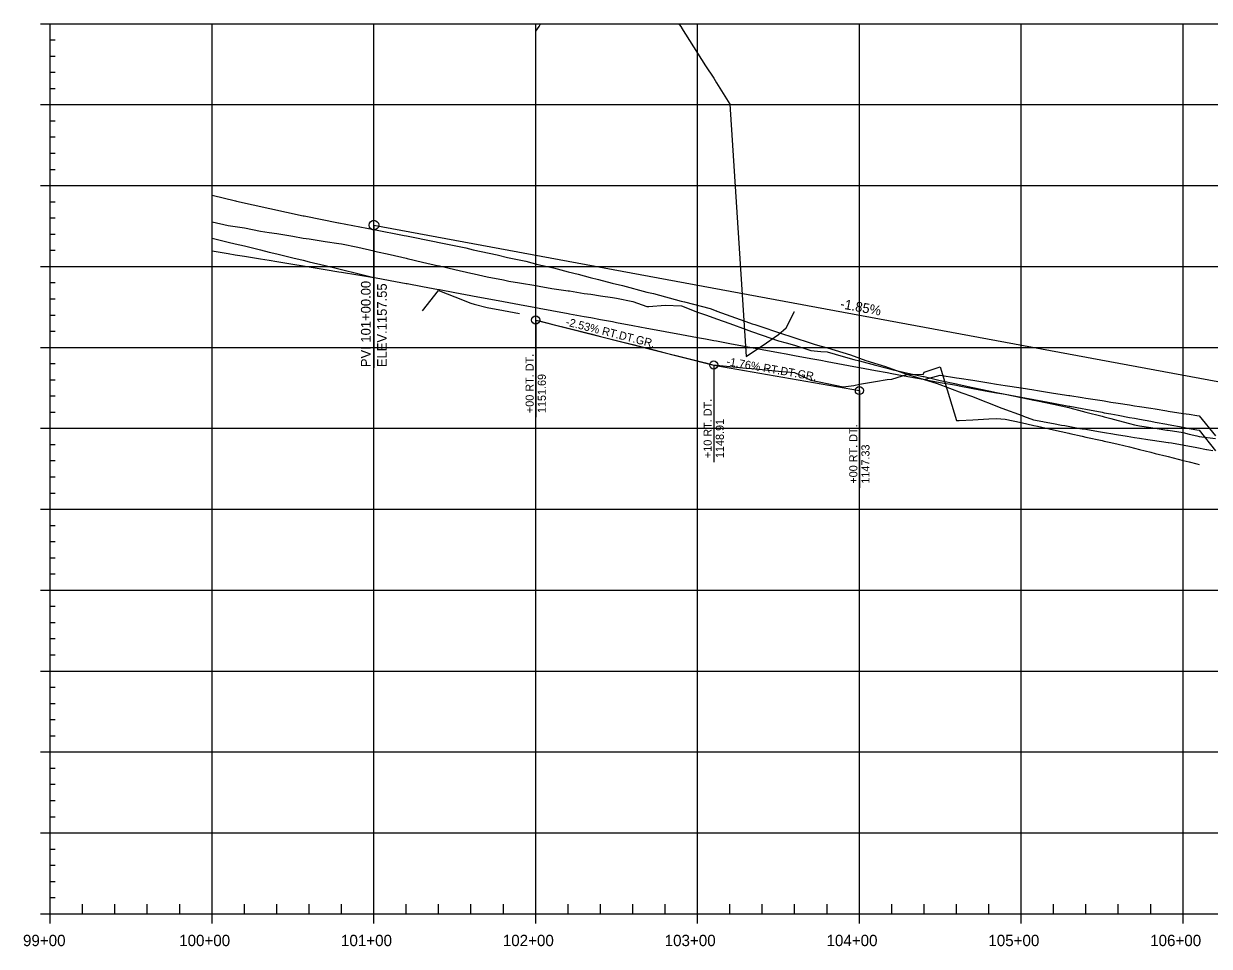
# Model space of a CAD drawing. Extents: x 688474 to 694748, y 765018 to 767373.
# Drawn here: x 690837 to 691570, y 765790 to 766360 of the extents above; entities that cross this region are included whole.
import ezdxf

# ---------------------------------------------------------------- set-up
doc = ezdxf.new("R2010")
doc.units = 0
for name, color, linetype in [('30', 7, 'Continuous'), ('37', 7, 'Continuous'), ('R_Exist Surface', 7, 'Continuous'), ('R_Profile Work Left', 7, 'Continuous'), ('R_Profile Work Right', 7, 'Continuous'), ('R_Vert Alg', 7, 'Continuous'), ('R_Vert Alg Annot', 7, 'Continuous')]:
    doc.layers.add(name, color=color, linetype=linetype)

msp = doc.modelspace()

# ---------------------------------------------------------------- linework, layer by layer
at = {"layer": '37'}
for p, q in [((690847.59, 766359.92), (690853.59, 766359.92)), ((690847.59, 766359.92), (690853.59, 766359.92)), ((690853.59, 765809.92), (690853.59, 766359.92)), ((690853.59, 766359.92), (693453.59, 766359.92)), ((690853.59, 766359.92), (693453.59, 766359.92)), ((690953.59, 765809.92), (690953.59, 766359.92)), ((691053.59, 765809.92), (691053.59, 766359.92)), ((691153.59, 765809.92), (691153.59, 766359.92)), ((691253.59, 765809.92), (691253.59, 766359.92)), ((691353.59, 765809.92), (691353.59, 766359.92)), ((691453.59, 765809.92), (691453.59, 766359.92)), ((691553.59, 765809.92), (691553.59, 766359.92)), ((690853.59, 766349.92), (690856.59, 766349.92)), ((690853.59, 766339.92), (690856.59, 766339.92)), ((690853.59, 766329.92), (690856.59, 766329.92)), ((690853.59, 766319.92), (690856.59, 766319.92)), ((690847.59, 766309.92), (690853.59, 766309.92)), ((690853.59, 766309.92), (693453.59, 766309.92)), ((690853.59, 766299.92), (690856.59, 766299.92)), ((690853.59, 766289.92), (690856.59, 766289.92)), ((690853.59, 766279.92), (690856.59, 766279.92)), ((690853.59, 766269.92), (690856.59, 766269.92)), ((690847.59, 766259.92), (690853.59, 766259.92)), ((690853.59, 766259.92), (693453.59, 766259.92)), ((690853.59, 766249.92), (690856.59, 766249.92)), ((690853.59, 766239.92), (690856.59, 766239.92)), ((690853.59, 766229.92), (690856.59, 766229.92)), ((690853.59, 766219.92), (690856.59, 766219.92)), ((690847.59, 766209.92), (690853.59, 766209.92)), ((690853.59, 766209.92), (693453.59, 766209.92)), ((690853.59, 766199.92), (690856.59, 766199.92)), ((690853.59, 766189.92), (690856.59, 766189.92)), ((690853.59, 766179.92), (690856.59, 766179.92)), ((690853.59, 766169.92), (690856.59, 766169.92)), ((690847.59, 766159.92), (690853.59, 766159.92)), ((690853.59, 766159.92), (693453.59, 766159.92)), ((690853.59, 766149.92), (690856.59, 766149.92)), ((690853.59, 766139.92), (690856.59, 766139.92)), ((690853.59, 766129.92), (690856.59, 766129.92)), ((690853.59, 766119.92), (690856.59, 766119.92)), ((690847.59, 766109.92), (690853.59, 766109.92)), ((690853.59, 766109.92), (693453.59, 766109.92)), ((690853.59, 766099.92), (690856.59, 766099.92)), ((690853.59, 766089.92), (690856.59, 766089.92)), ((690853.59, 766079.92), (690856.59, 766079.92)), ((690853.59, 766069.92), (690856.59, 766069.92)), ((690847.59, 766059.92), (690853.59, 766059.92)), ((690853.59, 766059.92), (693453.59, 766059.92)), ((690853.59, 766049.92), (690856.59, 766049.92)), ((690853.59, 766039.92), (690856.59, 766039.92)), ((690853.59, 766029.92), (690856.59, 766029.92)), ((690853.59, 766019.92), (690856.59, 766019.92)), ((690847.59, 766009.92), (690853.59, 766009.92)), ((690853.59, 766009.92), (693453.59, 766009.92)), ((690853.59, 765999.92), (690856.59, 765999.92)), ((690853.59, 765989.92), (690856.59, 765989.92)), ((690853.59, 765979.92), (690856.59, 765979.92)), ((690853.59, 765969.92), (690856.59, 765969.92)), ((690847.59, 765959.92), (690853.59, 765959.92)), ((690853.59, 765959.92), (693453.59, 765959.92)), ((690853.59, 765949.92), (690856.59, 765949.92)), ((690853.59, 765939.92), (690856.59, 765939.92)), ((690853.59, 765929.92), (690856.59, 765929.92)), ((690853.59, 765919.92), (690856.59, 765919.92)), ((690847.59, 765909.92), (690853.59, 765909.92)), ((690853.59, 765909.92), (693453.59, 765909.92)), ((690853.59, 765899.92), (690856.59, 765899.92)), ((690853.59, 765889.92), (690856.59, 765889.92)), ((690853.59, 765879.92), (690856.59, 765879.92)), ((690853.59, 765869.92), (690856.59, 765869.92)), ((690847.59, 765859.92), (690853.59, 765859.92)), ((690853.59, 765859.92), (693453.59, 765859.92)), ((690853.59, 765849.92), (690856.59, 765849.92)), ((690853.59, 765839.92), (690856.59, 765839.92)), ((690853.59, 765829.92), (690856.59, 765829.92)), ((690853.59, 765819.92), (690856.59, 765819.92)), ((690847.59, 765809.92), (690853.59, 765809.92)), ((690853.59, 765809.92), (693453.59, 765809.92)), ((690853.59, 765803.92), (690853.59, 765809.92)), ((690873.59, 765809.92), (690873.59, 765815.92)), ((690893.59, 765809.92), (690893.59, 765815.92)), ((690913.59, 765809.92), (690913.59, 765815.92)), ((690933.59, 765809.92), (690933.59, 765815.92)), ((690953.59, 765803.92), (690953.59, 765809.92)), ((690973.59, 765809.92), (690973.59, 765815.92)), ((690993.59, 765809.92), (690993.59, 765815.92)), ((691013.59, 765809.92), (691013.59, 765815.92)), ((691033.59, 765809.92), (691033.59, 765815.92)), ((691053.59, 765803.92), (691053.59, 765809.92)), ((691073.59, 765809.92), (691073.59, 765815.92)), ((691093.59, 765809.92), (691093.59, 765815.92)), ((691113.59, 765809.92), (691113.59, 765815.92)), ((691133.59, 765809.92), (691133.59, 765815.92)), ((691153.59, 765803.92), (691153.59, 765809.92)), ((691173.59, 765809.92), (691173.59, 765815.92)), ((691193.59, 765809.92), (691193.59, 765815.92)), ((691213.59, 765809.92), (691213.59, 765815.92)), ((691233.59, 765809.92), (691233.59, 765815.92)), ((691253.59, 765803.92), (691253.59, 765809.92)), ((691273.59, 765809.92), (691273.59, 765815.92)), ((691293.59, 765809.92), (691293.59, 765815.92)), ((691313.59, 765809.92), (691313.59, 765815.92)), ((691333.59, 765809.92), (691333.59, 765815.92)), ((691353.59, 765803.92), (691353.59, 765809.92)), ((691373.59, 765809.92), (691373.59, 765815.92)), ((691393.59, 765809.92), (691393.59, 765815.92)), ((691413.59, 765809.92), (691413.59, 765815.92)), ((691433.59, 765809.92), (691433.59, 765815.92)), ((691453.59, 765803.92), (691453.59, 765809.92)), ((691473.59, 765809.92), (691473.59, 765815.92)), ((691493.59, 765809.92), (691493.59, 765815.92)), ((691513.59, 765809.92), (691513.59, 765815.92)), ((691533.59, 765809.92), (691533.59, 765815.92)), ((691553.59, 765803.92), (691553.59, 765809.92))]:
    msp.add_line(p, q, dxfattribs=at)
at = {"layer": 'R_Exist Surface'}
msp.add_lwpolyline([(690953.59, 766253.9), (690968.1, 766250.39), (690968.66, 766250.28), (690989.27, 766245.77), (691009.97, 766241.23), (691010.43, 766241.14), (691031.77, 766236.97), (691032.01, 766236.93), (691053.54, 766232.73), (691053.59, 766232.72), (691072.32, 766229.06), (691073.73, 766228.74), (691091.11, 766225.3), (691093.86, 766224.67), (691110.38, 766221.35), (691115.02, 766220.19), (691129.7, 766217.18), (691136.24, 766215.52), (691147.49, 766213.09), (691154.94, 766211.17), (691164.56, 766209.05), (691173.69, 766206.67), (691179.76, 766205.22), (691187.25, 766203.16), (691192.42, 766201.91), (691200.75, 766199.61), (691207.2, 766198.07), (691222.15, 766194.12), (691226.37, 766193.11), (691243.55, 766188.53), (691245.53, 766188.05), (691261.31, 766183.86), (691265.03, 766182.47), (691265.27, 766182.4), (691265.52, 766182.33), (691285.79, 766174.99), (691287.3, 766174.56), (691288.92, 766174.1), (691307.32, 766167.87), (691310.09, 766167.1), (691326.17, 766161.71), (691329.92, 766160.67), (691333.91, 766159.57), (691348.09, 766155.27), (691357.62, 766151.87), (691369.74, 766148.13), (691382.65, 766143.43), (691393.02, 766140.25), (691401.69, 766137.59), (691416.92, 766131.74), (691422.79, 766129.81), (691441.7, 766122.36), (691454.23, 766117.76), (691455.08, 766117.47), (691461.2, 766115.19), (691467.01, 766114.07), (691467.68, 766113.97), (691473.58, 766112.85), (691478.5, 766111.92), (691480.56, 766111.59), (691489.91, 766109.85), (691491.27, 766109.64), (691493.43, 766109.3), (691501.25, 766107.86), (691506.28, 766107.11), (691508.97, 766106.62), (691512.49, 766105.98), (691519.1, 766105.01), (691523.63, 766104.2), (691526.67, 766103.77), (691531.91, 766103.02), (691534.68, 766102.53), (691544.37, 766101.2), (691544.69, 766101.15), (691546.39, 766100.86), (691562.07, 766098), (691568.09, 766096.89), (691568.31, 766096.85), (691571.98, 766096.17)], dxfattribs=at)
at = {"layer": 'R_Profile Work Left'}
for points in [[(690953.59, 766237.4), (690963.59, 766235.3), (690967.83, 766234.61), (690973.59, 766233.69), (690983.59, 766231.8), (690988.92, 766230.96), (690993.59, 766230.23), (691003.59, 766228.59), (691010, 766227.49), (691013.59, 766226.94), (691023.59, 766225.4), (691032, 766224.2), (691033.59, 766223.98), (691043.59, 766221.89), (691053.59, 766219.55), (691054, 766219.46), (691063.59, 766217.25), (691073.59, 766214.97), (691074.12, 766214.85), (691083.59, 766212.67), (691093.59, 766210.37), (691094.23, 766210.23), (691103.59, 766208.08), (691113.59, 766205.8), (691115.58, 766205.34), (691123.59, 766203.49), (691133.59, 766201.56), (691136.93, 766200.82), (691143.59, 766199.78), (691153.59, 766198.06), (691155.68, 766197.7), (691163.59, 766196.34), (691173.59, 766194.9), (691174.43, 766194.76), (691183.59, 766193.2), (691187.73, 766192.76), (691193.59, 766191.76), (691201.04, 766190.69), (691203.59, 766190.29), (691213.59, 766188.23), (691222.33, 766185.07), (691223.59, 766185.17), (691233.59, 766185.93), (691243.59, 766185.52), (691243.63, 766185.51), (691253.59, 766181.75), (691258.59, 766180.1), (691263.59, 766178.25), (691265.33, 766177.61), (691273.59, 766174.71), (691283.59, 766171.04), (691287.03, 766169.78), (691293.59, 766167.54), (691303.59, 766164.04), (691308.37, 766162.71), (691313.59, 766161.36), (691313.6, 766161.35), (691323.59, 766157.94), (691329.72, 766157.34), (691333.59, 766157.17), (691343.59, 766154.37), (691350.21, 766152.38), (691353.59, 766151.53), (691363.59, 766148.89), (691370.69, 766146.99), (691373.59, 766146.34), (691383.59, 766144.07), (691392.92, 766141.99), (691393.59, 766141.84)], [(690953.59, 766227.42), (690963.59, 766224.99), (690967.83, 766223.96), (690973.59, 766222.56), (690983.59, 766220.13), (690988.92, 766218.84), (690993.59, 766217.7), (691003.59, 766215.27), (691010, 766213.71), (691013.59, 766212.84), (691023.59, 766210.41), (691032, 766208.36), (691033.59, 766207.98), (691043.59, 766205.54), (691053.59, 766203.11), (691054, 766203.04), (691063.59, 766201.26), (691073.59, 766199.41), (691074.12, 766199.31), (691083.59, 766197.56), (691093.59, 766195.71), (691094.23, 766195.59), (691103.59, 766193.86), (691113.59, 766192), (691115.58, 766191.63), (691123.59, 766190.15), (691133.59, 766188.3), (691136.93, 766187.68), (691143.59, 766186.45), (691153.59, 766184.6), (691155.68, 766184.21), (691163.59, 766182.75), (691173.59, 766180.89), (691174.43, 766180.74), (691183.59, 766179.04), (691187.73, 766178.28), (691193.59, 766177.19), (691201.04, 766175.81), (691203.59, 766175.34), (691213.59, 766173.49), (691222.33, 766171.87), (691223.59, 766171.64), (691233.59, 766169.78), (691243.59, 766167.93), (691243.63, 766167.93), (691253.59, 766166.08), (691258.59, 766165.16), (691263.59, 766164.23), (691265.33, 766163.91), (691273.59, 766162.38), (691283.59, 766160.53), (691287.03, 766159.89), (691293.59, 766158.68), (691303.59, 766156.82), (691308.37, 766155.94), (691313.59, 766154.97), (691313.6, 766154.97), (691323.59, 766153.12), (691329.72, 766151.98), (691333.59, 766151.27), (691343.59, 766149.42), (691350.21, 766148.19), (691353.59, 766147.57), (691363.59, 766145.71), (691370.69, 766144.4), (691373.59, 766143.86), (691383.59, 766142.01), (691392.92, 766140.28), (691393.59, 766140.16), (691403.59, 766142.71), (691413.59, 766141.14), (691415.15, 766140.89), (691423.59, 766139.56), (691433.59, 766137.99), (691438.24, 766137.26), (691443.59, 766136.42), (691453.59, 766134.85), (691461.33, 766133.63), (691463.59, 766133.28), (691473.58, 766131.71), (691473.59, 766131.71), (691483.08, 766130.22), (691483.59, 766130.14), (691491.27, 766128.93), (691493.59, 766128.56), (691503.59, 766126.99), (691504.85, 766126.79), (691508.97, 766126.15), (691513.59, 766125.42), (691520.56, 766124.32), (691523.59, 766123.85), (691526.67, 766123.36), (691533.59, 766122.28), (691536.27, 766121.86), (691543.59, 766120.71), (691544.37, 766120.58), (691553.59, 766119.13), (691557.35, 766118.54), (691562.07, 766117.8), (691563.59, 766117.56), (691573.59, 766105.16)], [(691393.59, 766141.84), (691403.59, 766139.52), (691413.59, 766137.33), (691415.15, 766137), (691423.59, 766135.16), (691433.59, 766133.03), (691438.24, 766132.03), (691443.59, 766130.9), (691453.59, 766128.86), (691461.33, 766127.3), (691463.59, 766126.84), (691473.58, 766124.77), (691473.59, 766124.77), (691483.08, 766122.66), (691483.59, 766122.53), (691491.27, 766120.56), (691493.59, 766119.96), (691503.59, 766117.34), (691504.85, 766117.01), (691508.97, 766115.95), (691513.59, 766114.72), (691520.56, 766112.85), (691523.59, 766112.06), (691526.67, 766111.37), (691533.59, 766110.4), (691536.27, 766110.02), (691543.59, 766108.79), (691544.37, 766108.7), (691553.59, 766107.26), (691557.35, 766106.37), (691562.07, 766105.2), (691563.59, 766104.79), (691573.59, 766103.54)]]:
    msp.add_lwpolyline(points, dxfattribs=at)
at = {"layer": 'R_Profile Work Right'}
for points in [[(691153.59, 766355.28), (691155.68, 766358.21), (691156.61, 766359.92)], [(691242.02, 766359.92), (691243.59, 766357.48), (691243.63, 766357.42), (691253.59, 766341.77), (691258.59, 766333.98), (691263.59, 766326.19), (691265.33, 766323.34), (691273.59, 766310.17), (691283.59, 766154.34)], [(690953.59, 766219.53), (690963.59, 766217.89), (690967.83, 766217.19), (690973.59, 766216.25), (690983.59, 766214.6), (690988.92, 766213.73), (690993.59, 766212.96), (691003.59, 766211.32), (691010, 766210.27), (691013.59, 766209.68), (691023.59, 766208.04), (691032, 766206.66), (691033.59, 766206.4), (691043.59, 766204.75), (691053.59, 766203.11), (691054, 766203.04), (691063.59, 766201.26), (691073.59, 766199.41), (691074.12, 766199.31), (691083.59, 766197.56), (691093.59, 766195.71), (691094.23, 766195.59), (691103.59, 766193.86), (691113.59, 766192), (691115.58, 766191.63), (691123.59, 766190.15), (691133.59, 766188.3), (691136.93, 766187.68), (691143.59, 766186.45), (691153.59, 766184.6), (691155.68, 766184.21), (691163.59, 766182.75), (691173.59, 766180.89), (691174.43, 766180.74), (691183.59, 766179.04), (691187.73, 766178.28), (691193.59, 766177.19), (691201.04, 766175.81), (691203.59, 766175.34), (691213.59, 766173.49), (691222.33, 766171.87), (691223.59, 766171.64), (691233.59, 766169.78), (691243.59, 766167.93), (691243.63, 766167.93), (691253.59, 766166.08), (691258.59, 766165.16), (691263.59, 766164.23), (691265.33, 766163.91), (691273.59, 766162.38), (691283.59, 766160.53), (691287.03, 766159.89), (691293.59, 766158.68), (691303.59, 766156.82), (691308.37, 766155.94), (691313.59, 766154.97), (691313.6, 766154.97), (691323.59, 766153.12), (691329.72, 766151.98), (691333.59, 766151.27), (691343.59, 766149.42), (691350.21, 766148.19), (691353.59, 766147.57), (691363.59, 766145.71), (691370.69, 766144.4), (691373.59, 766143.86), (691383.59, 766142.01), (691392.92, 766140.28), (691393.59, 766140.16), (691403.59, 766138.31), (691413.59, 766136.46), (691415.15, 766136.17), (691423.59, 766134.6), (691433.59, 766132.75), (691438.24, 766131.89), (691443.59, 766130.9), (691453.59, 766129.05), (691461.33, 766127.62), (691463.59, 766127.2), (691473.58, 766125.35), (691473.59, 766125.35), (691483.08, 766123.59), (691483.59, 766123.5), (691491.27, 766122.07), (691493.59, 766121.64), (691503.59, 766119.79), (691504.85, 766119.56), (691508.97, 766118.8), (691513.59, 766117.94), (691520.56, 766116.65), (691523.59, 766116.09), (691526.67, 766115.52), (691533.59, 766114.24), (691536.27, 766113.74), (691543.59, 766112.39), (691544.37, 766112.24), (691553.59, 766110.53), (691557.35, 766109.84), (691562.07, 766108.96), (691563.59, 766108.68), (691573.59, 766096)], [(691083.59, 766182.56), (691093.59, 766195.04)], [(691093.59, 766195.04), (691094.23, 766194.8), (691103.59, 766191.18), (691113.59, 766187.3), (691115.58, 766186.53), (691123.59, 766184.46), (691133.59, 766182.76), (691136.93, 766182.13), (691143.59, 766180.87)], [(691153.59, 766176.82), (691155.68, 766176.29), (691163.59, 766174.29), (691173.59, 766171.77), (691174.43, 766171.55), (691183.59, 766169.24), (691187.73, 766168.19), (691193.59, 766166.71), (691201.04, 766164.83), (691203.59, 766164.18), (691213.59, 766161.66), (691222.33, 766159.45), (691223.59, 766159.13), (691233.59, 766156.6), (691243.59, 766154.07), (691243.63, 766154.07), (691253.59, 766151.55), (691258.59, 766150.28), (691263.59, 766149.02), (691265.33, 766148.86), (691273.59, 766148.09), (691283.59, 766147.15), (691287.03, 766146.83), (691293.59, 766146.22), (691303.59, 766145.29), (691308.37, 766144.84), (691313.59, 766144.35), (691313.6, 766144.35)], [(691283.59, 766154.34), (691287.03, 766156.6), (691293.59, 766160.92), (691303.59, 766167.9), (691308.37, 766172.07), (691313.59, 766182.13), (691313.6, 766182.16)], [(691383.59, 766143.33), (691392.92, 766143.25), (691393.59, 766144.6), (691403.59, 766147.84)], [(691403.59, 766147.84), (691413.59, 766114.63), (691415.15, 766114.72), (691423.59, 766115.21), (691433.59, 766115.79), (691438.24, 766116.05), (691443.59, 766115.62), (691453.59, 766113.39), (691461.33, 766111.66), (691463.59, 766111.16), (691473.58, 766108.93), (691473.59, 766108.93), (691483.08, 766106.82), (691483.59, 766106.71), (691491.27, 766105.01), (691493.59, 766104.49), (691503.59, 766102.28), (691504.85, 766102), (691508.97, 766101.08), (691513.59, 766100.06), (691520.56, 766098.39), (691523.59, 766097.62), (691526.67, 766096.85), (691533.59, 766095.11), (691536.27, 766094.43), (691543.59, 766092.59), (691544.37, 766092.4), (691553.59, 766090.08), (691557.35, 766089.13), (691562.07, 766087.95), (691563.59, 766087.56)], [(691313.6, 766144.35), (691323.59, 766139.63), (691329.72, 766138.39), (691333.59, 766137.67), (691343.59, 766135.62), (691350.21, 766136.4), (691353.59, 766137.19), (691363.59, 766138.81), (691370.69, 766140.1), (691373.59, 766140.33), (691383.59, 766143.33)]]:
    msp.add_lwpolyline(points, dxfattribs=at)
at = {"layer": 'R_Vert Alg'}
for p, q in [((691053.59, 766235.38), (691761.59, 766104.29)), ((691153.59, 766176.82), (691263.59, 766149.02)), ((691263.59, 766149.02), (691353.59, 766133.22))]:
    msp.add_line(p, q, dxfattribs=at)
for centre, radius in [((691053.59, 766235.42), 3), ((691153.59, 766176.82), 2.5), ((691263.59, 766149.02), 2.5), ((691353.59, 766133.22), 2.5)]:
    msp.add_circle(centre, radius, dxfattribs=at)
at = {"layer": 'R_Vert Alg Annot'}
for p, q in [((691053.59, 766235.42), (691053.59, 766147.27)), ((691153.59, 766176.82), (691153.59, 766116.82)), ((691263.59, 766149.02), (691263.59, 766089.02)), ((691353.59, 766133.22), (691353.59, 766073.22))]:
    msp.add_line(p, q, dxfattribs=at)

# ---------------------------------------------------------------- texts
at = {"layer": '30'}
for s, p in [('99+00', (690836.78, 765789.92)), ('100+00', (690933.28, 765789.92)), ('101+00', (691033.28, 765789.92)), ('102+00', (691133.28, 765789.92)), ('103+00', (691233.28, 765789.92)), ('104+00', (691333.28, 765789.92)), ('105+00', (691433.28, 765789.92)), ('106+00', (691533.28, 765789.92))]:
    msp.add_text(s, height=7, dxfattribs=at).set_placement(p)
at = {"layer": 'R_Vert Alg Annot'}
for s, height, rotation, p in [('PVI 101+00.00', 6, 90, (691051.59, 766147.7)), ('ELEV.1157.55', 6, 90, (691061.59, 766147.7)), ('-1.85%', 6, 349.51008, (691341.43, 766184.12)), ('-2.53% RT.DT.GR.', 5, 345.81678, (691171.81, 766173.5)), ('+00 RT. DT.', 5, 90, (691152.34, 766119.32)), ('-1.76% RT.DT.GR.', 5, 350.04287, (691271.13, 766148.97)), ('1151.69', 5, 90, (691159.84, 766119.32)), ('+10 RT. DT.', 5, 90, (691262.34, 766091.52)), ('1148.91', 5, 90, (691269.84, 766091.52)), ('+00 RT. DT.', 5, 90, (691352.34, 766075.72)), ('1147.33', 5, 90, (691359.84, 766075.72))]:
    msp.add_text(s, height=height, rotation=rotation, dxfattribs=at).set_placement(p)

doc.saveas('drawing.dxf')
